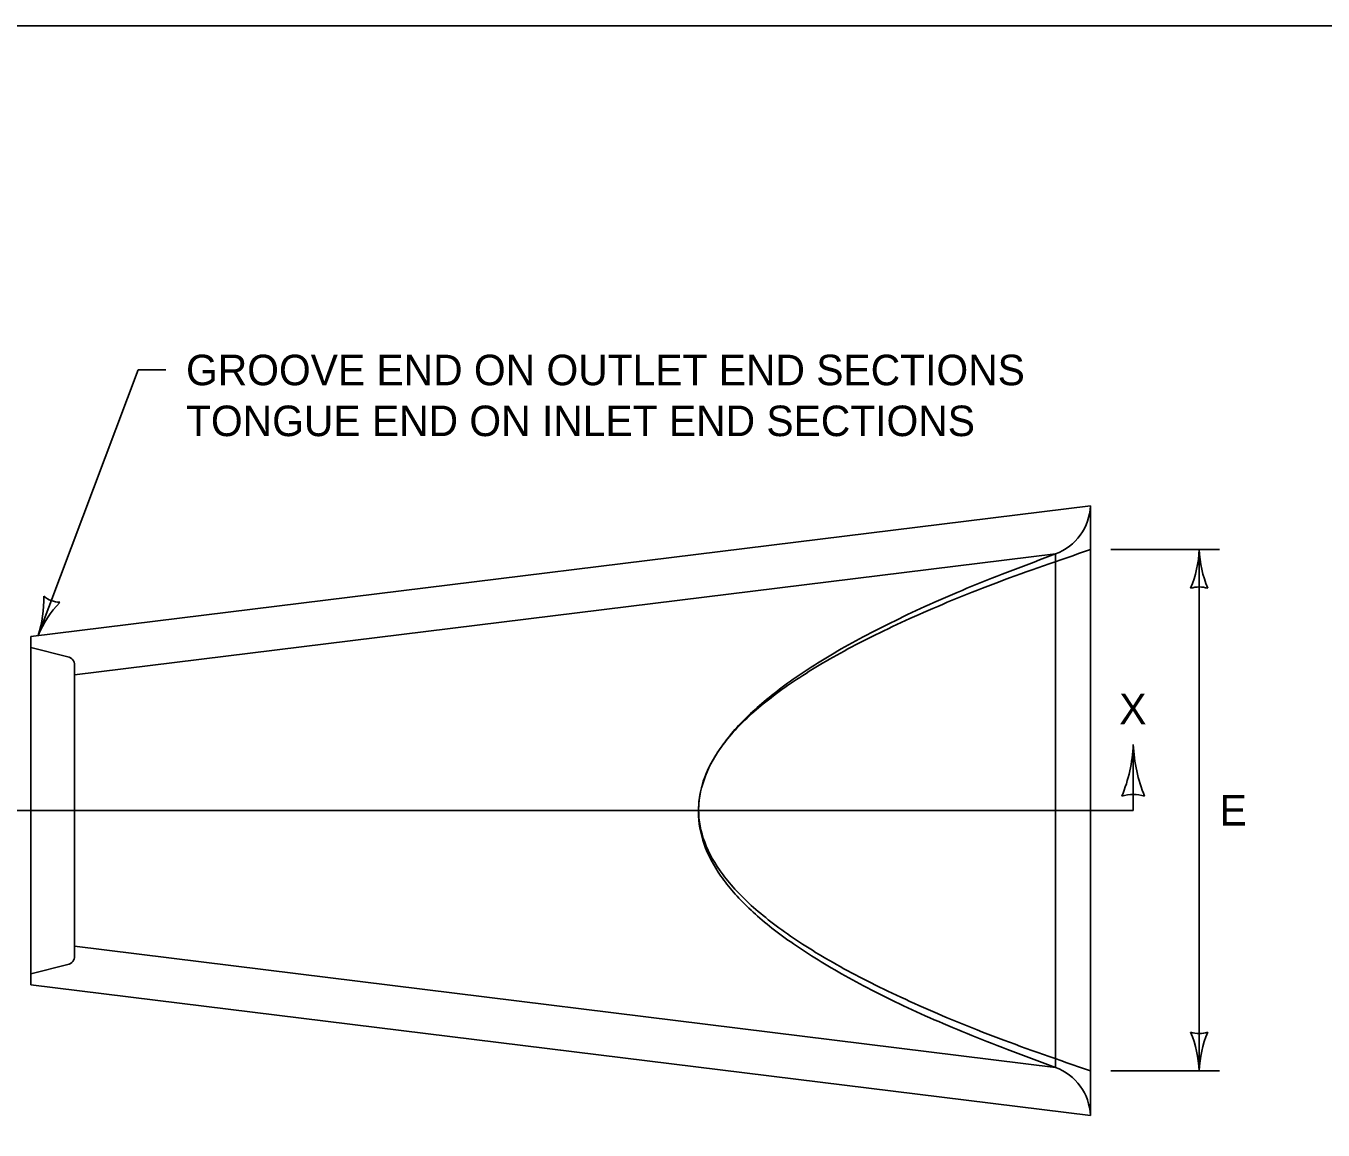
# Model space of a CAD drawing. Extents: x 49991.4 to 50022.1, y 49985 to 50011.4.
# Drawn here: x 50000.674 to 50003.224, y 49996.829 to 49998.999 of the extents above; entities that cross this region are included whole.
import ezdxf

# ---------------------------------------------------------------- set-up
doc = ezdxf.new("R2010")
doc.units = 0
for name, color, linetype in [('Level 1', 7, 'Continuous'), ('Level 2', 7, 'Continuous'), ('Level 3', 7, 'Continuous'), ('Level 4', 7, 'Continuous'), ('Level 6', 7, 'Continuous')]:
    doc.layers.add(name, color=color, linetype=linetype)

msp = doc.modelspace()

# ---------------------------------------------------------------- linework, layer by layer
at = {"layer": 'Level 1'}
for p, q in [((50000.6836, 49997.7995), (50002.7668, 49998.0564)), ((50002.7668, 49998.0564), (50002.7668, 49996.8577)), ((50002.6983, 49997.9616), (50002.6983, 49996.9525)), ((50000.6836, 49997.7995), (50000.6836, 49997.1146)), ((50000.6836, 49997.1146), (50002.7668, 49996.8577))]:
    msp.add_line(p, q, dxfattribs=at)
msp.add_lwpolyline([(49999.3835, 49998.9992), (50016.7501, 49998.9992), (50016.7501, 49987.7988), (49999.3835, 49987.7988)], close=True, dxfattribs=at)
for centre, start, end in [((50002.6624, 49998.0597), 290.0929, 358.1486), ((50002.6624, 49996.8544), 1.8514, 69.9071)]:
    msp.add_arc(centre, 0.1044, start, end, dxfattribs=at)
for points in [[(50002.6983, 49997.9616), (50001.2942, 49997.4525), (50002.6983, 49996.9525)], [(50002.7668, 49997.9701), (50001.226, 49997.46), (50002.7668, 49996.9456)]]:
    msp.add_open_spline(points, degree=2, dxfattribs=at)
at = {"layer": 'Level 3'}
for p, q in [((50000.8947, 49998.3231), (50000.6976, 49997.8012)), ((50000.9485, 49998.3231), (50000.8947, 49998.3231)), ((50002.8068, 49997.9701), (50003.0208, 49997.9701)), ((50002.9808, 49997.9701), (50002.9808, 49996.9456)), ((50002.8068, 49996.9456), (50003.0208, 49996.9456))]:
    msp.add_line(p, q, dxfattribs=at)
for centre, radius, start, end in [((50002.7587, 49997.9793), 0.2223, 337.456, 357.6395), ((50003.2135, 49997.9816), 0.233, 182.8273, 202.0772), ((50000.4758, 49997.8727), 0.233, 342.1298, 1.3797), ((50000.7429, 49997.9212), 0.0548, 231.4413, 267.1637), ((50002.9808, 49997.8419), 0.0548, 72.1388, 107.8612), ((50000.9021, 49997.7141), 0.2223, 136.7585, 156.942), ((50002.5549, 49997.599), 0.2964, 337.456, 357.6395), ((50003.1614, 49997.6021), 0.3107, 182.8273, 202.0772), ((50002.8511, 49997.4158), 0.073, 72.1388, 107.8612), ((50002.9808, 49997.0738), 0.0548, 252.1388, 287.8612), ((50002.7481, 49996.9341), 0.233, 2.8273, 22.0772), ((50003.2029, 49996.9364), 0.2223, 157.456, 177.6395)]:
    msp.add_arc(centre, radius, start, end, dxfattribs=at)
at = {"layer": 'Level 4'}
for p, q in [((50000.7692, 49997.7238), (50002.6983, 49997.9616)), ((50000.6836, 49997.778), (50000.7562, 49997.7596)), ((50000.7692, 49997.743), (50000.7692, 49997.1711)), ((50000.7692, 49997.1904), (50002.6983, 49996.9525)), ((50000.6836, 49997.1361), (50000.7562, 49997.1545))]:
    msp.add_line(p, q, dxfattribs=at)
for centre, start, end in [((50000.7521, 49997.743), 0, 75.8416), ((50000.7521, 49997.1711), 284.1569, 0)]:
    msp.add_arc(centre, 0.0171, start, end, dxfattribs=at)
at = {"layer": 'Level 6'}
for p, q in [((50002.8511, 49997.457), (50002.8511, 49997.5868)), ((50000.5813, 49997.457), (50002.8511, 49997.457))]:
    msp.add_line(p, q, dxfattribs=at)

# ---------------------------------------------------------------- texts
at = {"layer": 'Level 2'}
for s, p in [('GROOVE END ON OUTLET END SECTIONS', (50000.9885, 49998.2931)), ('TONGUE END ON INLET END SECTIONS', (50000.9885, 49998.1931)), ('X', (50002.8236, 49997.6268)), ('E', (50003.0208, 49997.4278))]:
    msp.add_text(s, height=0.06, dxfattribs=at).set_placement(p)

doc.saveas('drawing.dxf')
